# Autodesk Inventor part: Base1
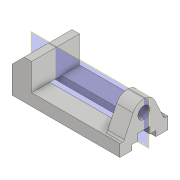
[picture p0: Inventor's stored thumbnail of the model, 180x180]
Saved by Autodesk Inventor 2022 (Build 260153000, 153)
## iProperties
Created: 2016-03
Part Number: Base1
Material: Generic
Document SubType Name: Modeling
Designer: Sandeep
Density: 1 g/cm^3
Appearance: Default
Author: Sandeep
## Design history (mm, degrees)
sketch "Sketch1"
  geometry: L1 (0, 0)-(0, 16); L2 (0, 16)-(118, 16); L3 (118, 16)-(118, 52); L4 (118, 52)-(144, 52); L5 (144, 52)-(144, 0); L6 (144, 0)-(0, 0)
  constraints: 12 end point, 3 perpendicular, 1 vertical
  dimensions: "d1" = 144 distance of L5.end L1.start; "d2" = 26 distance of L3.end L4.end; "d3" = 16 distance between parallel lines of L6 L2; "d4" = 36 distance between parallel lines of L2 L4
extrude "Extrusion1" new body sketch "Sketch1" stored distance "d5" = 64; taper "d6" = 0 deg
chamfer "Chamfer1" distance "d7" = 16; stored, may be unused: second distance "d8" = 16, angle "d9" = 45 deg
sketch "Sketch4"
  geometry: 1 further point
sketch "Sketch5"
  geometry: L1 (-16, 5.02)-(-42.762, 17.499); L2 (-42.762, 46.501)-(-16, 58.98); L3 (-52, 64)-(-52, 0) reference; L4 (-16, 32)-(-54.774, 32); L5 (-52, 64)-(-16, 64) reference; L6 (-16, 64)-(-16, 0) reference; L7 (-16, 5.02)-(-16, 58.98); L8 (0, 64)-(0, 0) reference; A1 r 16 centre (-36, 32) between (-42.762, 46.501) and (-42.762, 17.499); 1 further point
  constraints: 8 end point, 3 point on line, 3 tangent, 2 point on circle, 1 centre point, 1 collinear, 1 horizontal, 1 other
  dimensions: "d21" = 50 deg angle of L2 L1; "d22" = 36 distance from line of L8 A1.centre
extrude "Extrusion2" join sketch "Sketch5" distance "d23" = 22; taper "d24" = 0 deg
fillet "Fillet1" dims "d25" = 3
sketch "Sketch6"
  geometry: L1 (-36, 64)-(-36, 0) reference; C1 r 8 at (-36, 32); A1 r 16 centre (-36, 32) between (-42.762, 46.501) and (-42.762, 17.499) reference; 1 further point
  constraints: 1 centre point, 1 concentric, 1 midpoint
  dimensions: "d26" = 16 diameter of C1
extrude "Extrusion3" cut sketch "Sketch6" distance "d27" = 22; taper "d28" = 0 deg
sketch "Sketch7"
  geometry: L1 (0, 0)-(0, 64) reference; L2 (0, 16)-(-7, 16); L3 (-7, 16)-(-7, 24); L4 (-7, 24)-(-16, 24); L5 (-16, 3.109)-(-16, 60.891) reference; L6 (-16, 24)-(-16, 40); L7 (-7, 40)-(-7, 48); L8 (-7, 48)-(0, 48); L9 (0, 48)-(0, 16); L10 (-7, 40)-(-16, 40); L11 (-44, 32)-(-36, 32); 1 further point
  constraints: 18 end point, 6 point on line, 4 perpendicular, 2 horizontal, 1 collinear, 1 horizontal alignment, 4 other
  dimensions: "d29" = 32 distance between parallel lines of L2 L8; "d30" = 7 distance of L7.end L8.end; "d45" = 16 distance between parallel lines of L10 L4
extrude "Extrusion4" cut sketch "Sketch7" distance "d31" = 167.75; taper "d32" = 0 deg
sketch "Sketch8"
  geometry: L1 (144, 0)-(144, -16) reference; L2 (0, 0)-(144, 0) reference; L3 (0, -16)-(0, 0) reference; 3 further points
  dimensions: "d33" = 70 distance of point (108, -10) point (38, -10); "d35" = 10 distance from line of L2 point (108, -10); "d36" = 10 distance from line of L2 point (38, -10); "d46" = 38 distance from line of L3 point (38, -10)
hole "Hole1" sketch "Sketch8" at (38, -10), (108, -10) diameter "d37" = 4.917; stored, may be unused: countersink angle "d41" = 90 deg, drill point angle "d43" = 118 deg; dims "d38" = 12, "d39" = 4, "d40" = 2, "d42" = 10
workplane "Work Plane1"
mirror "Mirror1"
body "Solid1"
other parameters: "d10" = 16, "d13" = 7, "d14" = 16, "d44" = -32
